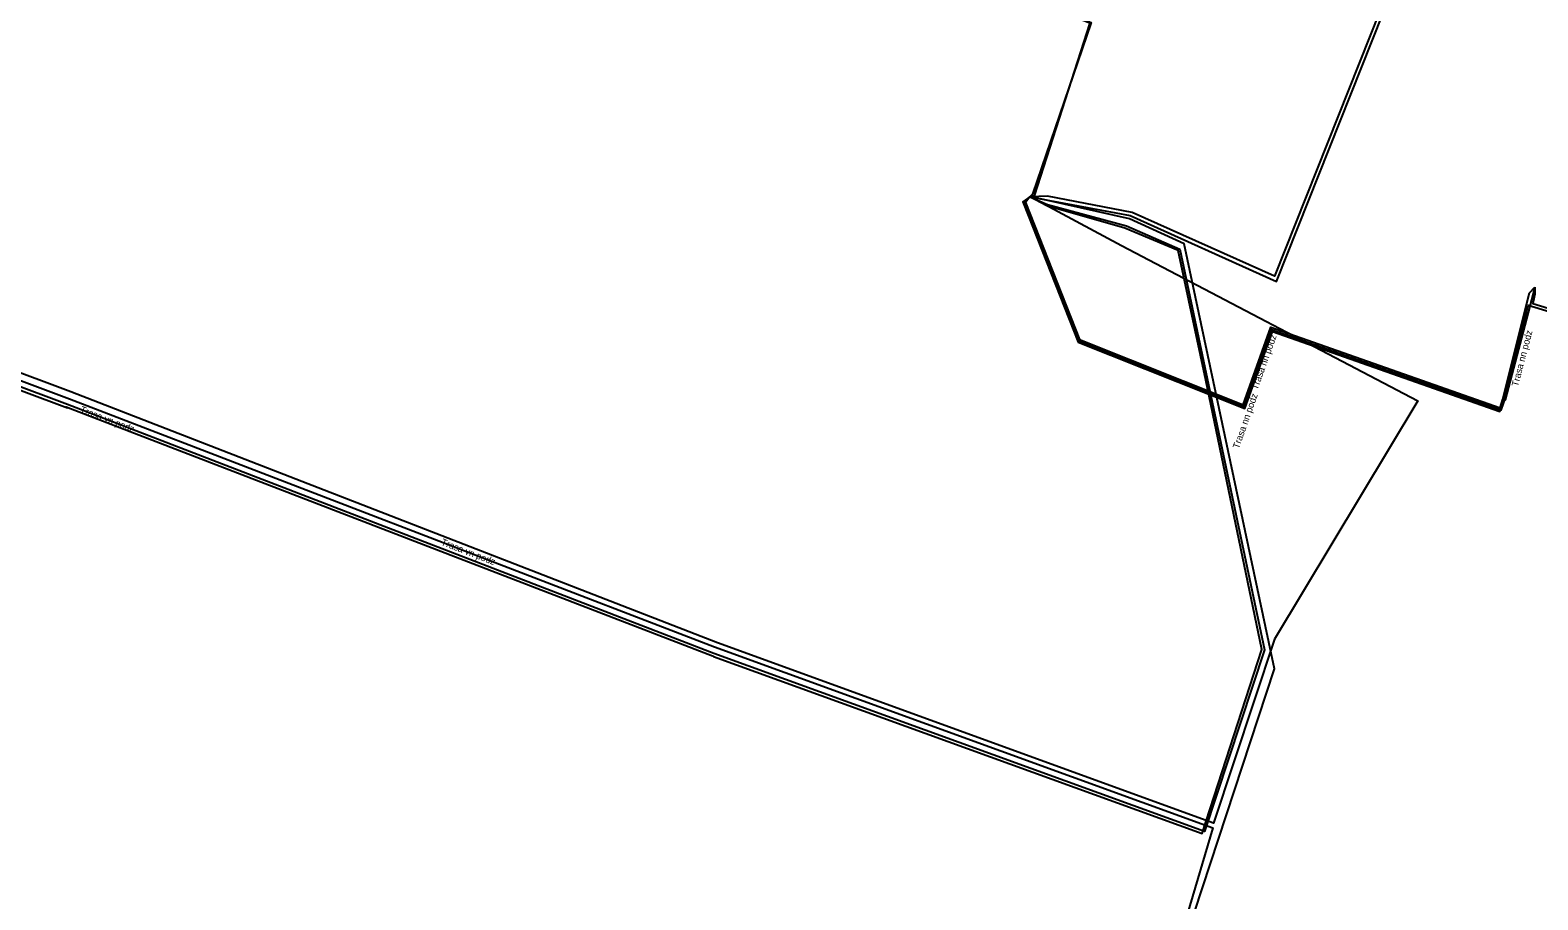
# Model space of a CAD drawing. Extents: x -875087 to -874407, y -1056142 to -1055396.
# Drawn here: x -874745.8 to -874634, y -1055727.9 to -1055663.4 of the extents above; entities that cross this region are included whole.
import ezdxf

# ---------------------------------------------------------------- set-up
doc = ezdxf.new("R2010")
doc.units = 0
for name, color, linetype in [('Popiskový text - Ostatní atributy Trasy', 7, 'Continuous'), ('Spojnice NN', 7, 'Continuous'), ('Spojnice VN', 7, 'Continuous')]:
    doc.layers.add(name, color=color, linetype=linetype)

msp = doc.modelspace()

# ---------------------------------------------------------------- linework, layer by layer
at = {"layer": 'Spojnice NN'}
for points in [[(-874612.48, -1055559.82), (-874612.35, -1055560.11), (-874609.64, -1055561.04), (-874615.01, -1055584.78), (-874653.49, -1055681.61), (-874664.04, -1055676.9), (-874670.32, -1055675.68), (-874671.63, -1055675.74)], [(-874698.87, -1055643.39), (-874698.77, -1055643.79), (-874700.84, -1055649.71), (-874667.17, -1055662.84), (-874671.32, -1055675.67), (-874671.63, -1055675.74)], [(-874698.87, -1055643.39), (-874698.74, -1055643.91), (-874700.73, -1055649.65), (-874667.07, -1055662.82), (-874671.42, -1055675.53), (-874671.63, -1055675.74)], [(-874634.17, -1055682.43), (-874634.19, -1055682.95), (-874634.32, -1055683.65), (-874614.15, -1055689.79), (-874599.17, -1055694.31), (-874586.99, -1055697.42), (-874581.03, -1055677.56), (-874578.66, -1055669.75), (-874577.85, -1055667.03), (-874575.19, -1055670.33), (-874564.57, -1055672.34), (-874564.56, -1055671.87)], [(-874671.63, -1055675.74), (-874670.33, -1055676.31), (-874664.47, -1055677.9), (-874660.5, -1055679.61), (-874654.24, -1055709.33), (-874658.68, -1055722.79), (-874695.05, -1055709.61), (-874743, -1055691.15), (-874768.77, -1055681.49), (-874774.59, -1055690.01), (-874781.56, -1055700.37), (-874783.65, -1055703.3), (-874788.62, -1055713.02), (-874797.64, -1055726.39), (-874799.59, -1055730.03), (-874808.94, -1055745.54), (-874820.99, -1055764.94), (-874838.65, -1055793.01), (-874841.25, -1055791.16), (-874841.27, -1055791.14)], [(-874838.49, -1055793.12), (-874820.8, -1055765.01), (-874809.61, -1055746.92), (-874799.54, -1055730.32), (-874797.66, -1055726.83), (-874788.45, -1055713.06), (-874783.51, -1055703.37), (-874781.37, -1055700.5), (-874774.35, -1055690.1), (-874768.72, -1055681.78), (-874742.98, -1055691.38), (-874743.1, -1055691.32), (-874695.15, -1055709.78), (-874695.09, -1055709.83), (-874658.86, -1055722.94), (-874654.42, -1055709.31), (-874658.57, -1055689.33), (-874660.63, -1055679.72), (-874664.59, -1055678.06), (-874670.38, -1055676.41), (-874671.63, -1055675.74)], [(-874671.63, -1055675.74), (-874672.14, -1055676.1), (-874672.09, -1055676.23), (-874668.05, -1055686.51), (-874655.68, -1055691.44), (-874653.63, -1055685.73), (-874636.77, -1055691.66), (-874636.4, -1055690.52), (-874634.68, -1055683.78), (-874614.19, -1055689.95), (-874599.12, -1055694.49), (-874587.05, -1055697.61), (-874589.41, -1055705.68), (-874592.97, -1055717.79), (-874593.11, -1055718.28), (-874600.61, -1055742.94), (-874589.46, -1055747.15), (-874589.08, -1055746.44), (-874588.99, -1055746.23)], [(-874671.63, -1055675.74), (-874672.05, -1055676.13), (-874668.03, -1055686.43), (-874656.48, -1055690.98), (-874655.72, -1055691.31), (-874653.71, -1055685.57), (-874636.68, -1055691.56), (-874636.47, -1055691), (-874636.41, -1055690.8)], [(-874671.63, -1055675.74), (-874671.94, -1055676.16), (-874667.95, -1055686.33), (-874656.47, -1055690.88), (-874655.81, -1055691.16), (-874653.77, -1055685.4), (-874636.75, -1055691.38), (-874636.56, -1055690.75), (-874634.57, -1055682.87), (-874634.17, -1055682.43)], [(-874636.41, -1055690.8), (-874636.35, -1055690.78), (-874634.29, -1055682.91), (-874634.17, -1055682.43)]]:
    msp.add_lwpolyline(points, dxfattribs=at)
at = {"layer": 'Spojnice VN'}
for points in [[(-874671.62, -1055675.74), (-874664.18, -1055677.12), (-874653.33, -1055682.01), (-874614.75, -1055584.92), (-874608.13, -1055555.88), (-874592.2, -1055524.96), (-874588.97, -1055504.43), (-874585.67, -1055482.27), (-874580.15, -1055462.49), (-874586.24, -1055458.27), (-874612, -1055448.91), (-874634.66, -1055436.86), (-874633.37, -1055428.2), (-874633.11, -1055424.46), (-874629.83, -1055396.03)], [(-874577.52, -1055665.5), (-874603.15, -1055750.63), (-874659.41, -1055728.79), (-874653.48, -1055710.73), (-874660.19, -1055679.23), (-874664.25, -1055677.37), (-874671.5, -1055675.74)], [(-874671.56, -1055675.74), (-874664.83, -1055679.35), (-874642.85, -1055690.87), (-874653.48, -1055708.53), (-874658.01, -1055722.19), (-874694.8, -1055708.8), (-874742.75, -1055690.2), (-874769.05, -1055680.37), (-874784.29, -1055703), (-874789.15, -1055712.76), (-874798.81, -1055726.69), (-874800.18, -1055726.09), (-874805.16, -1055720.78), (-874805.36, -1055720.41)], [(-874805.36, -1055720.41), (-874805.24, -1055720.8), (-874800.38, -1055726.55), (-874798.72, -1055727.23), (-874788.98, -1055712.98), (-874783.92, -1055703.11), (-874768.94, -1055680.92), (-874742.85, -1055690.72), (-874695, -1055709.1), (-874658.06, -1055722.54), (-874659.97, -1055728.95), (-874656.4, -1055730.43)]]:
    msp.add_lwpolyline(points, dxfattribs=at)

# ---------------------------------------------------------------- texts
at = {"layer": 'Popiskový text - Ostatní atributy Trasy'}
for s, rotation, p in [('Trasa nn podz', 70.5495, (-874654.74, -1055690.09)), ('Trasa nn podz', 75.3275, (-874635.43, -1055689.84)), ('Trasa nn podz', 70.7324, (-874656.13, -1055694.46)), ('Trasa vn podz', 338.9922, (-874742.1, -1055691.7)), ('Trasa vn podz', 338.7977, (-874715.33, -1055701.53))]:
    msp.add_text(s, height=0.5, rotation=rotation, dxfattribs=at).set_placement(p)

doc.saveas('drawing.dxf')
